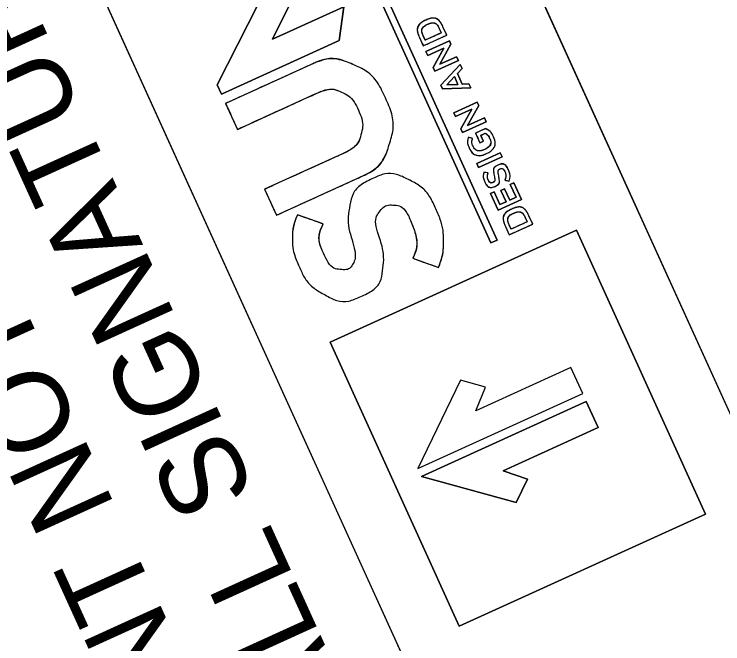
# Model space of a CAD drawing. Extents: x 2096093 to 2099001, y 683546 to 685907.
# Drawn here: x 2097556.64 to 2097600.26, y 685405.5 to 685444.23 of the extents above; entities that cross this region are included whole.
import ezdxf

# ---------------------------------------------------------------- set-up
doc = ezdxf.new("R2010")
doc.units = 0
for name, color, linetype in [('Scratch_Level_4', 7, 'Continuous'), ('Sheet Block Title CELL', 7, 'Continuous'), ('Sheet Layout Plan Border', 7, 'Continuous'), ('Sheet Sticker Exception Certification CELL', 7, 'Continuous')]:
    doc.layers.add(name, color=color, linetype=linetype)

msp = doc.modelspace()

# ---------------------------------------------------------------- linework, layer by layer
at = {"layer": 'Scratch_Level_4'}
msp.add_lwpolyline([(2097576.737, 685472.345), (2098256.773, 685779.318), (2098363.728, 685544.169), (2098430.064, 685574.342), (2098911.143, 684517.116), (2097955.365, 684082.388), (2097417.224, 685265.53), (2097411.626, 685277.836), (2097412.446, 685278.179), (2097621.751, 685373.38)], close=True, dxfattribs=at)
at = {"layer": 'Sheet Block Title CELL'}
for p, q in [((2097581.978, 685443.865), (2097581.974, 685443.863)), ((2097582.094, 685443.61), (2097582.098, 685443.611)), ((2097584.856, 685436.585), (2097584.594, 685436.652)), ((2097585.596, 685435.911), (2097585.592, 685435.909)), ((2097585.712, 685435.655), (2097585.716, 685435.657)), ((2097586.412, 685434.944), (2097586.408, 685434.943)), ((2097585.809, 685434.462), (2097585.558, 685434.506)), ((2097586.543, 685434.71), (2097586.547, 685434.712)), ((2097586.852, 685434.026), (2097587.1, 685433.963)), ((2097586.11, 685433.873), (2097586.105, 685433.871)), ((2097586.239, 685433.638), (2097586.243, 685433.64)), ((2097575.666, 685431.325), (2097574.075, 685431.884)), ((2097587.265, 685432.242), (2097587.261, 685432.24)), ((2097587.381, 685431.987), (2097587.385, 685431.988)), ((2097581.173, 685429.213), (2097582.764, 685428.654))]:
    msp.add_line(p, q, dxfattribs=at)
for points in [[(2097599.439, 685363.231), (2097522.114, 685533.236), (2097544.426, 685543.384), (2097621.751, 685373.38)], [(2097584.035, 685406.584), (2097576.089, 685424.053), (2097591.251, 685430.949), (2097599.197, 685413.48)], [(2097581.497, 685416.279), (2097591.635, 685420.89), (2097590.908, 685422.487), (2097585.061, 685419.827), (2097585.658, 685421.293), (2097584.124, 685421.717)]]:
    msp.add_lwpolyline(points, close=True, dxfattribs=at)
for points in [[(2097568.771, 685469.031), (2097586.372, 685430.333), (2097585.988, 685430.158), (2097568.386, 685468.856), (2097568.771, 685469.031)], [(2097568.386, 685468.856), (2097585.988, 685430.158), (2097586.372, 685430.333), (2097568.771, 685469.031), (2097568.386, 685468.856)], [(2097569.141, 685439.88), (2097572.27, 685446.085), (2097573.988, 685445.604), (2097572.553, 685442.695), (2097576.943, 685444.691), (2097576.655, 685442.618), (2097569.397, 685439.316), (2097569.141, 685439.88)], [(2097569.397, 685439.316), (2097576.655, 685442.618), (2097576.943, 685444.691), (2097572.553, 685442.695), (2097573.988, 685445.604), (2097572.27, 685446.085), (2097569.141, 685439.88), (2097569.397, 685439.316)], [(2097581.591, 685442.8), (2097581.826, 685442.283), (2097583.27, 685442.941), (2097583.035, 685443.457)], [(2097582.804, 685443.352), (2097582.929, 685443.079), (2097581.946, 685442.632), (2097581.822, 685442.905)], [(2097582.537, 685440.72), (2097582.434, 685440.946), (2097583.096, 685442.142), (2097582.097, 685441.688), (2097581.988, 685441.928), (2097583.432, 685442.585), (2097583.525, 685442.381), (2097582.845, 685441.149), (2097583.873, 685441.617), (2097583.982, 685441.377), (2097582.537, 685440.72)], [(2097583.982, 685441.377), (2097583.873, 685441.617), (2097582.845, 685441.149), (2097583.525, 685442.381), (2097583.432, 685442.585), (2097581.988, 685441.928), (2097582.097, 685441.688), (2097583.096, 685442.142), (2097582.434, 685440.946), (2097582.537, 685440.72), (2097583.982, 685441.377)], [(2097574.887, 685441.122), (2097569.658, 685438.743), (2097570.385, 685437.146), (2097575.17, 685439.323)], [(2097583.014, 685439.643), (2097582.912, 685439.868), (2097584.089, 685441.14), (2097584.207, 685440.882), (2097583.922, 685440.583), (2097584.22, 685439.928), (2097584.633, 685439.944), (2097584.747, 685439.695), (2097583.014, 685439.643)], [(2097584.747, 685439.695), (2097584.633, 685439.944), (2097584.22, 685439.928), (2097583.922, 685440.583), (2097584.207, 685440.882), (2097584.089, 685441.14), (2097582.912, 685439.868), (2097583.014, 685439.643), (2097584.747, 685439.695)], [(2097583.737, 685440.392), (2097583.268, 685439.89), (2097583.954, 685439.915), (2097583.737, 685440.392)], [(2097583.954, 685439.915), (2097583.268, 685439.89), (2097583.737, 685440.392), (2097583.954, 685439.915)], [(2097584.247, 685436.96), (2097584.145, 685437.185), (2097584.806, 685438.382), (2097583.807, 685437.928), (2097583.698, 685438.167), (2097585.143, 685438.824), (2097585.236, 685438.62), (2097584.555, 685437.389), (2097585.583, 685437.856), (2097585.692, 685437.617), (2097584.247, 685436.96)], [(2097585.692, 685437.617), (2097585.583, 685437.856), (2097584.555, 685437.389), (2097585.236, 685438.62), (2097585.143, 685438.824), (2097583.698, 685438.167), (2097583.807, 685437.928), (2097584.806, 685438.382), (2097584.145, 685437.185), (2097584.247, 685436.96), (2097585.692, 685437.617)], [(2097585.645, 685437.189), (2097585.038, 685436.913), (2097585.306, 685436.324), (2097585.527, 685436.424), (2097585.366, 685436.779), (2097585.636, 685436.902)], [(2097576.846, 685435.637), (2097572.061, 685433.461), (2097572.787, 685431.863), (2097578.016, 685434.242)], [(2097585.232, 685434.794), (2097585.121, 685435.038), (2097586.566, 685435.695), (2097586.677, 685435.452), (2097585.232, 685434.794)], [(2097586.677, 685435.452), (2097586.566, 685435.695), (2097585.121, 685435.038), (2097585.232, 685434.794), (2097586.677, 685435.452)], [(2097586.427, 685432.168), (2097585.959, 685433.196), (2097586.186, 685433.299), (2097586.543, 685432.515), (2097586.918, 685432.686), (2097586.602, 685433.381), (2097586.829, 685433.484), (2097587.146, 685432.789), (2097587.533, 685432.966), (2097587.172, 685433.759), (2097587.399, 685433.863), (2097587.871, 685432.825), (2097586.427, 685432.168)], [(2097587.871, 685432.825), (2097587.399, 685433.863), (2097587.172, 685433.759), (2097587.533, 685432.966), (2097587.146, 685432.789), (2097586.829, 685433.484), (2097586.602, 685433.381), (2097586.918, 685432.686), (2097586.543, 685432.515), (2097586.186, 685433.299), (2097585.959, 685433.196), (2097586.427, 685432.168), (2097587.871, 685432.825)], [(2097586.877, 685431.177), (2097587.112, 685430.66), (2097588.557, 685431.317), (2097588.322, 685431.834)], [(2097588.091, 685431.729), (2097588.215, 685431.456), (2097587.233, 685431.009), (2097587.109, 685431.282)], [(2097576.089, 685424.053), (2097584.035, 685406.584), (2097599.197, 685413.48), (2097591.251, 685430.949), (2097576.089, 685424.053)], [(2097581.497, 685416.279), (2097591.635, 685420.89), (2097590.908, 685422.487), (2097585.061, 685419.827), (2097585.658, 685421.293), (2097584.124, 685421.717), (2097581.497, 685416.279)], [(2097581.72, 685415.787), (2097591.858, 685420.399), (2097592.585, 685418.802), (2097586.737, 685416.142), (2097588.234, 685415.629), (2097587.546, 685414.194), (2097581.72, 685415.787)], [(2097587.546, 685414.194), (2097588.234, 685415.629), (2097586.737, 685416.142), (2097592.585, 685418.802), (2097591.858, 685420.399), (2097581.72, 685415.787), (2097587.546, 685414.194)]]:
    msp.add_lwpolyline(points, dxfattribs=at)
for points, degree in [([(2097581.826, 685442.283), (2097581.826, 685442.283), (2097581.591, 685442.8), (2097581.591, 685442.8), (2097581.393, 685443.235), (2097581.568, 685443.678), (2097581.974, 685443.863), (2097581.974, 685443.863), (2097581.978, 685443.865), (2097581.978, 685443.865), (2097582.385, 685444.05), (2097582.837, 685443.893), (2097583.035, 685443.457), (2097583.035, 685443.457), (2097583.27, 685442.941), (2097583.27, 685442.941), (2097583.27, 685442.941), (2097581.826, 685442.283), (2097581.826, 685442.283)], 3), ([(2097581.974, 685443.863), (2097581.568, 685443.678), (2097581.393, 685443.235), (2097581.591, 685442.8)], 2), ([(2097581.946, 685442.632), (2097581.946, 685442.632), (2097582.929, 685443.079), (2097582.929, 685443.079), (2097582.929, 685443.079), (2097582.804, 685443.352), (2097582.804, 685443.352), (2097582.672, 685443.643), (2097582.381, 685443.74), (2097582.098, 685443.611), (2097582.098, 685443.611), (2097582.094, 685443.61), (2097582.094, 685443.61), (2097581.812, 685443.481), (2097581.69, 685443.196), (2097581.822, 685442.905), (2097581.822, 685442.905), (2097581.946, 685442.632), (2097581.946, 685442.632)], 3), ([(2097583.035, 685443.457), (2097582.837, 685443.893), (2097582.385, 685444.05), (2097581.978, 685443.865)], 2), ([(2097582.098, 685443.611), (2097582.381, 685443.74), (2097582.672, 685443.643), (2097582.804, 685443.352)], 2), ([(2097581.822, 685442.905), (2097581.69, 685443.196), (2097581.812, 685443.481), (2097582.094, 685443.61)], 2), ([(2097572.061, 685433.461), (2097572.061, 685433.461), (2097576.846, 685435.637), (2097576.846, 685435.637), (2097577.475, 685435.923), (2097577.854, 685436.314), (2097577.988, 685436.802), (2097578.123, 685437.291), (2097578.068, 685437.803), (2097577.826, 685438.335), (2097577.585, 685438.866), (2097577.245, 685439.222), (2097576.788, 685439.441), (2097576.331, 685439.661), (2097575.799, 685439.608), (2097575.17, 685439.323), (2097575.17, 685439.323), (2097570.385, 685437.146), (2097570.385, 685437.146), (2097570.385, 685437.146), (2097569.658, 685438.743), (2097569.658, 685438.743), (2097569.658, 685438.743), (2097574.887, 685441.122), (2097574.887, 685441.122), (2097575.737, 685441.508), (2097576.597, 685441.527), (2097577.486, 685441.14), (2097578.375, 685440.754), (2097579.041, 685440.075), (2097579.492, 685439.083), (2097579.943, 685438.091), (2097580.022, 685437.132), (2097579.729, 685436.208), (2097579.437, 685435.284), (2097578.866, 685434.628), (2097578.016, 685434.242), (2097578.016, 685434.242), (2097572.787, 685431.863), (2097572.787, 685431.863), (2097572.787, 685431.863), (2097572.061, 685433.461), (2097572.061, 685433.461)], 3), ([(2097578.016, 685434.242), (2097578.866, 685434.628), (2097579.437, 685435.284), (2097579.729, 685436.208), (2097580.022, 685437.132), (2097579.943, 685438.091), (2097579.492, 685439.083), (2097579.041, 685440.075), (2097578.375, 685440.754), (2097577.486, 685441.14), (2097576.597, 685441.527), (2097575.737, 685441.508), (2097574.887, 685441.122)], 3), ([(2097575.17, 685439.323), (2097575.799, 685439.608), (2097576.331, 685439.661), (2097576.788, 685439.441), (2097577.245, 685439.222), (2097577.585, 685438.866), (2097577.826, 685438.335), (2097578.068, 685437.803), (2097578.123, 685437.291), (2097577.988, 685436.802), (2097577.854, 685436.314), (2097577.475, 685435.923), (2097576.846, 685435.637)], 3), ([(2097585.716, 685435.657), (2097585.716, 685435.657), (2097585.712, 685435.655), (2097585.712, 685435.655), (2097585.308, 685435.471), (2097584.83, 685435.612), (2097584.64, 685436.03), (2097584.53, 685436.272), (2097584.533, 685436.452), (2097584.594, 685436.652), (2097584.594, 685436.652), (2097584.856, 685436.585), (2097584.856, 685436.585), (2097584.81, 685436.435), (2097584.798, 685436.303), (2097584.878, 685436.126), (2097584.994, 685435.871), (2097585.315, 685435.783), (2097585.592, 685435.909), (2097585.592, 685435.909), (2097585.596, 685435.911), (2097585.596, 685435.911), (2097585.893, 685436.046), (2097586.026, 685436.334), (2097585.898, 685436.617), (2097585.838, 685436.747), (2097585.741, 685436.846), (2097585.636, 685436.902), (2097585.636, 685436.902), (2097585.366, 685436.779), (2097585.366, 685436.779), (2097585.366, 685436.779), (2097585.527, 685436.424), (2097585.527, 685436.424), (2097585.527, 685436.424), (2097585.306, 685436.324), (2097585.306, 685436.324), (2097585.306, 685436.324), (2097585.038, 685436.913), (2097585.038, 685436.913), (2097585.038, 685436.913), (2097585.645, 685437.189), (2097585.645, 685437.189), (2097585.829, 685437.108), (2097586.021, 685436.959), (2097586.133, 685436.714), (2097586.33, 685436.28), (2097586.137, 685435.849), (2097585.716, 685435.657)], 3), ([(2097585.716, 685435.657), (2097586.137, 685435.849), (2097586.33, 685436.28), (2097586.133, 685436.714), (2097586.021, 685436.959), (2097585.829, 685437.108), (2097585.645, 685437.189)], 3), ([(2097584.594, 685436.652), (2097584.533, 685436.452), (2097584.53, 685436.272), (2097584.64, 685436.03), (2097584.83, 685435.612), (2097585.308, 685435.471), (2097585.712, 685435.655)], 3), ([(2097585.636, 685436.902), (2097585.741, 685436.846), (2097585.838, 685436.747), (2097585.898, 685436.617), (2097586.026, 685436.334), (2097585.893, 685436.046), (2097585.596, 685435.911)], 3), ([(2097585.592, 685435.909), (2097585.315, 685435.783), (2097584.994, 685435.871), (2097584.878, 685436.126), (2097584.798, 685436.303), (2097584.81, 685436.435), (2097584.856, 685436.585)], 3), ([(2097587.1, 685433.963), (2097587.1, 685433.963), (2097586.852, 685434.026), (2097586.852, 685434.026), (2097586.911, 685434.214), (2097586.918, 685434.379), (2097586.84, 685434.55), (2097586.772, 685434.7), (2097586.655, 685434.761), (2097586.547, 685434.712), (2097586.547, 685434.712), (2097586.543, 685434.71), (2097586.543, 685434.71), (2097586.44, 685434.664), (2097586.409, 685434.583), (2097586.465, 685434.297), (2097586.524, 685433.969), (2097586.509, 685433.761), (2097586.243, 685433.64), (2097586.243, 685433.64), (2097586.239, 685433.638), (2097586.239, 685433.638), (2097585.991, 685433.525), (2097585.73, 685433.645), (2097585.605, 685433.92), (2097585.513, 685434.122), (2097585.504, 685434.312), (2097585.558, 685434.506), (2097585.558, 685434.506), (2097585.809, 685434.462), (2097585.809, 685434.462), (2097585.769, 685434.294), (2097585.774, 685434.146), (2097585.831, 685434.019), (2097585.896, 685433.876), (2097586.011, 685433.828), (2097586.105, 685433.871), (2097586.105, 685433.871), (2097586.11, 685433.873), (2097586.11, 685433.873), (2097586.221, 685433.924), (2097586.242, 685434.009), (2097586.186, 685434.307), (2097586.127, 685434.633), (2097586.168, 685434.834), (2097586.408, 685434.943), (2097586.408, 685434.943), (2097586.412, 685434.944), (2097586.412, 685434.944), (2097586.682, 685435.067), (2097586.936, 685434.937), (2097587.068, 685434.646), (2097587.165, 685434.434), (2097587.179, 685434.199), (2097587.1, 685433.963)], 3), ([(2097586.408, 685434.943), (2097586.168, 685434.834), (2097586.127, 685434.633), (2097586.186, 685434.307), (2097586.242, 685434.009), (2097586.221, 685433.924), (2097586.11, 685433.873)], 3), ([(2097587.1, 685433.963), (2097587.179, 685434.199), (2097587.165, 685434.434), (2097587.068, 685434.646), (2097586.936, 685434.937), (2097586.682, 685435.067), (2097586.412, 685434.944)], 3), ([(2097585.558, 685434.506), (2097585.504, 685434.312), (2097585.513, 685434.122), (2097585.605, 685433.92), (2097585.73, 685433.645), (2097585.991, 685433.525), (2097586.239, 685433.638)], 3), ([(2097586.105, 685433.871), (2097586.011, 685433.828), (2097585.896, 685433.876), (2097585.831, 685434.019), (2097585.774, 685434.146), (2097585.769, 685434.294), (2097585.809, 685434.462)], 3), ([(2097586.243, 685433.64), (2097586.509, 685433.761), (2097586.524, 685433.969), (2097586.465, 685434.297), (2097586.409, 685434.583), (2097586.44, 685434.664), (2097586.543, 685434.71)], 3), ([(2097586.547, 685434.712), (2097586.655, 685434.761), (2097586.772, 685434.7), (2097586.84, 685434.55), (2097586.918, 685434.379), (2097586.911, 685434.214), (2097586.852, 685434.026)], 3), ([(2097573.764, 685430.363), (2097573.763, 685430.855), (2097573.866, 685431.362), (2097574.075, 685431.884), (2097574.075, 685431.884), (2097575.666, 685431.325), (2097575.666, 685431.325), (2097575.384, 685430.769), (2097575.388, 685430.173), (2097575.678, 685429.535), (2097575.968, 685428.897), (2097576.31, 685428.561), (2097576.705, 685428.527), (2097577.099, 685428.493), (2097577.367, 685428.614), (2097577.508, 685428.892), (2097577.649, 685429.17), (2097577.63, 685429.653), (2097577.451, 685430.341), (2097577.218, 685431.047), (2097577.171, 685431.764), (2097577.309, 685432.489), (2097577.447, 685433.215), (2097577.941, 685433.77), (2097578.791, 685434.157), (2097579.456, 685434.459), (2097580.161, 685434.427), (2097580.908, 685434.059), (2097581.654, 685433.691), (2097582.205, 685433.117), (2097582.56, 685432.338), (2097582.897, 685431.598), (2097583.067, 685430.929), (2097583.071, 685430.332), (2097583.075, 685429.735), (2097582.972, 685429.176), (2097582.764, 685428.654), (2097582.764, 685428.654), (2097581.173, 685429.213), (2097581.173, 685429.213), (2097581.455, 685429.769), (2097581.44, 685430.489), (2097581.127, 685431.372), (2097580.805, 685432.081), (2097580.446, 685432.451), (2097580.053, 685432.484), (2097579.66, 685432.516), (2097579.346, 685432.373), (2097579.111, 685432.055), (2097578.877, 685431.737), (2097578.885, 685431.207), (2097579.133, 685430.465), (2097579.349, 685429.794), (2097579.411, 685429.117), (2097579.321, 685428.434), (2097579.23, 685427.752), (2097578.779, 685427.226), (2097577.966, 685426.856), (2097577.231, 685426.522), (2097576.504, 685426.556), (2097575.784, 685426.957), (2097575.064, 685427.359), (2097574.56, 685427.878), (2097574.27, 685428.516), (2097573.933, 685429.256), (2097573.764, 685429.872), (2097573.764, 685430.363)], 3), ([(2097582.764, 685428.654), (2097582.972, 685429.176), (2097583.075, 685429.735), (2097583.071, 685430.332), (2097583.067, 685430.929), (2097582.897, 685431.598), (2097582.56, 685432.338), (2097582.205, 685433.117), (2097581.654, 685433.691), (2097580.908, 685434.059), (2097580.161, 685434.427), (2097579.456, 685434.459), (2097578.791, 685434.157), (2097577.941, 685433.77), (2097577.447, 685433.215), (2097577.309, 685432.489), (2097577.171, 685431.764), (2097577.218, 685431.047), (2097577.451, 685430.341), (2097577.63, 685429.653), (2097577.649, 685429.17), (2097577.508, 685428.892), (2097577.367, 685428.614), (2097577.099, 685428.493), (2097576.705, 685428.527), (2097576.31, 685428.561), (2097575.968, 685428.897), (2097575.678, 685429.535), (2097575.388, 685430.173), (2097575.384, 685430.769), (2097575.666, 685431.325)], 3), ([(2097573.764, 685430.363), (2097573.764, 685429.872), (2097573.933, 685429.256), (2097574.27, 685428.516), (2097574.56, 685427.878), (2097575.064, 685427.359), (2097575.784, 685426.957), (2097576.504, 685426.556), (2097577.231, 685426.522), (2097577.966, 685426.856), (2097578.779, 685427.226), (2097579.23, 685427.752), (2097579.321, 685428.434), (2097579.411, 685429.117), (2097579.349, 685429.794), (2097579.133, 685430.465), (2097578.885, 685431.207), (2097578.877, 685431.737), (2097579.111, 685432.055), (2097579.346, 685432.373), (2097579.66, 685432.516), (2097580.053, 685432.484), (2097580.446, 685432.451), (2097580.805, 685432.081), (2097581.127, 685431.372), (2097581.44, 685430.489), (2097581.455, 685429.769), (2097581.173, 685429.213)], 3), ([(2097587.112, 685430.66), (2097587.112, 685430.66), (2097586.877, 685431.177), (2097586.877, 685431.177), (2097586.679, 685431.613), (2097586.854, 685432.055), (2097587.261, 685432.24), (2097587.261, 685432.24), (2097587.265, 685432.242), (2097587.265, 685432.242), (2097587.671, 685432.427), (2097588.124, 685432.27), (2097588.322, 685431.834), (2097588.322, 685431.834), (2097588.557, 685431.317), (2097588.557, 685431.317), (2097588.557, 685431.317), (2097587.112, 685430.66), (2097587.112, 685430.66)], 3), ([(2097588.322, 685431.834), (2097588.124, 685432.27), (2097587.671, 685432.427), (2097587.265, 685432.242)], 2), ([(2097574.075, 685431.884), (2097573.866, 685431.362), (2097573.763, 685430.855), (2097573.764, 685430.363)], 2), ([(2097587.261, 685432.24), (2097586.854, 685432.055), (2097586.679, 685431.613), (2097586.877, 685431.177)], 2), ([(2097587.233, 685431.009), (2097587.233, 685431.009), (2097588.215, 685431.456), (2097588.215, 685431.456), (2097588.215, 685431.456), (2097588.091, 685431.729), (2097588.091, 685431.729), (2097587.959, 685432.02), (2097587.668, 685432.117), (2097587.385, 685431.988), (2097587.385, 685431.988), (2097587.381, 685431.987), (2097587.381, 685431.987), (2097587.098, 685431.858), (2097586.976, 685431.573), (2097587.109, 685431.282), (2097587.109, 685431.282), (2097587.233, 685431.009), (2097587.233, 685431.009)], 3), ([(2097587.109, 685431.282), (2097586.976, 685431.573), (2097587.098, 685431.858), (2097587.381, 685431.987)], 2), ([(2097587.385, 685431.988), (2097587.668, 685432.117), (2097587.959, 685432.02), (2097588.091, 685431.729)], 2)]:
    msp.add_open_spline(points, degree=degree, dxfattribs=at)
at = {"layer": 'Sheet Layout Plan Border'}
msp.add_lwpolyline([(2097576.737, 685472.345), (2098256.773, 685779.318), (2098363.728, 685544.169), (2098430.064, 685574.342), (2098911.143, 684517.116), (2097955.365, 684082.388), (2097417.224, 685265.53), (2097411.626, 685277.836), (2097412.446, 685278.179), (2097621.751, 685373.38)], close=True, dxfattribs=at)
at = {"layer": 'Sheet Sticker Exception Certification CELL'}
msp.add_line((2097522.114, 685533.236), (2097599.439, 685363.231), dxfattribs=at)
msp.add_line((2097522.114, 685533.236), (2097599.439, 685363.231), dxfattribs=at)

# ---------------------------------------------------------------- texts
for s, p in [('UNLESS ALL SIGNATURES COMPLETED', (2097589.553, 685375.146)), ('UNLESS ALL SIGNATURES COMPLETED', (2097589.553, 685375.146)), ('DOCUMENT NOT CONSIDERED FINAL', (2097580.114, 685376.054)), ('DOCUMENT NOT CONSIDERED FINAL', (2097580.114, 685376.054))]:
    msp.add_text(s, height=5.13504, rotation=114.458, dxfattribs=at).set_placement(p)

doc.saveas('drawing.dxf')
